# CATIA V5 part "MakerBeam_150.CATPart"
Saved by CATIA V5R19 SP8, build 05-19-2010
Part number: Profilé Makebeam 150
Definition: Profilé Makebeam 150
Nomenclature: MakerBeam_100089
Bounding box of the stored display mesh (mm): x 0 to 150, y -5 to 5, z -5 to 5
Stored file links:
  D:\Documents\1_Travail\1 - ac-limoges.fr\ac-limoges.fr\Emmanuel Maynard - STI2D_Turgot\1 - IT-I2D\Activités_IT_Première\IT_3_Abris_bus\Maquettes numériques\Abribus_eleve\MakerBeam_150.CATPart
  C:\Program Files\Dassault Systemes\B19\win_b64\reffiles\standard\MetricThickPitch.txt
  D:\Documents\1_Travail\2- 2I2D\6 -  Ressources ITEC\Ressources Techniques\0-Maquettes numériques_Composants\Catalogue_Makeblock\Catalog_Makeblock\12_MakerBeam\TableMakerbeam.xls
  D:\Documents\1_Travail\2- 2I2D\6 -  Ressources ITEC\Ressources Techniques\0-Maquettes numériques_Composants\Catalogue_Makeblock\Catalog_Makeblock\12_MakerBeam\TableMakerbeam.txt
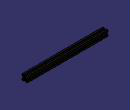
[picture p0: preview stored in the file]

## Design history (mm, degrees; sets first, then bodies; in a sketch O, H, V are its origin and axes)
Parameters
  Longueur = 150 mm
  `Désignation` = "Profilé Makebeam 150"
  `Référence` = "MakerBeam_100089"
AxisSystem1: origin (0, 0, 0), X (1, 0, 0), Y (0, 1, 0), Z (0, 0, 1)
Body1 (main body)
  Sketch1 on YZ plane of AxisSystem1, origin (0, 0, 0), H (0, 1, 0), V (0, 0, 1)
    line L1 (-5, 5) -> (-1.5, 5)
    point P1 (5, 5)
    point P2 (-5, 5)
    arc A1 centre (0, 0) radius 1.2 from (0, 1.2) to (-0.8485, 0.8485) ccw
    line L2 (-0.8485, 0.8485) -> (-5, 5)
    line L3 (0, 1.2) -> (0, 2)
    reference intersected line E1 through (0, 0) direction (-1, 0) from XY plane of AxisSystem1
    reference intersected line E2 through (0, 0) direction (0, 1) from ZX plane of AxisSystem1
    line L4 (-1.5, 5) -> (-1.5, 4)
    line L5 (-1.5, 4) -> (-3.2929, 4)
    line L6 (-3.2929, 4) -> (-1, 2)
    line L7 (-1, 2) -> (0, 2)
    reference projected line E3 through (0, 0) direction (0, 1) from edge [ZX plane of AxisSystem1 | YZ plane of AxisSystem1]
    radius A1 = 1.2
    distance L1 E1 = 5
    distance P2 E3 = 5
    distance L4 P2 = 3.5
    length L7 = 1
    distance L5 L1 = 1
    distance L7 L1 = 3
    angle L6 L3 = 48.903
    horizontal: L1 H, L5 H, L7 H
    vertical: L3 V, L4 V
    coincidence: L3 E2, L2 O
  Pad1: profile Sketch1, direction (1, 0, 0), length 150 {= Longueur}
  Fillet1: radius 0.2, on edge [face of Pad1 from Sketch1.L5 | face of Pad1 from Sketch1.L6]; edge [face of Pad1 from Sketch1.L6 | face of Pad1 from Sketch1.L7]; edge [face of Pad1 from Sketch1.L1 | face of Pad1 from Sketch1.L4]; edge [face of Pad1 from Sketch1.L4 | face of Pad1 from Sketch1.L5]
  Mirror1: of the body so far, about face of Pad1 from Sketch1.L2
  Fillet2: radius 0.2, on edge [face of Mirror1 | face of Pad1 from Sketch1.L1]
  Mirror2: of the body so far, about face of Mirror1
  Mirror3: of the body so far, about face of Pad1 from Sketch1.L3
  Sketch2 on face of Pad1, origin (150, 0.9666, 1.0824), H (0, 1, 0), V (0, 0, 1)
    point P1 (-0.9666, -1.0824)
    projected point E1 (-0.9666, -1.0824) from axis of face of Mirror3
    coincidence: E1 P1
  Hole1: placed by Sketch2, at (150, 0, 0) direction (-1, 0, 0), diameter 2.459, depth 10, threaded "M3", thread diameter 3, thread depth 8, pitch 0.5
  Sketch3 on face of Pad1, origin (0, -1.3866, 1.2369), H (0, 1, 0), V (0, 0, -1)
    point P1 (1.3866, 1.2369)
    reference projected point E1 (1.3866, 1.2369) from axis of face of Pad1
    coincidence: P1 E1
  Hole2: placed by Sketch3, at (0, 0, 0) direction (1, 0, 0), diameter 2.459, depth 10, threaded "M3", thread diameter 3, thread depth 8, pitch 0.5
Current feature: Mirror3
